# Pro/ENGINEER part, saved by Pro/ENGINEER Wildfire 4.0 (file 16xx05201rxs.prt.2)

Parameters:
  HERSTELLER = "Hersteller"
  NB = "16XX05201RXS"
  NN = "16-R"
  NT = "16 Series - Rigid"
  NBSYN = "$PN.$RIGS.$T."
  LINA = "16XX05201RXS"
  PN = "16XX05201"
  RIGS = "R"
  T = "XS"
  DIA = "5"
  WIDTH = "2"
  A = "2.44"
  B = "4.000"
  C = "3.75"
  WW1 = "2.000"
  T1 = "'XS','MR','PB','XA','CA','TM','NG','XI','PI','PD','XP','CH'"
  PN1 = "XS0520112"
  AXLE = "1"
  KT = "DUMMY"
